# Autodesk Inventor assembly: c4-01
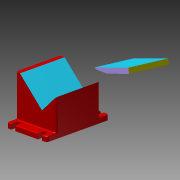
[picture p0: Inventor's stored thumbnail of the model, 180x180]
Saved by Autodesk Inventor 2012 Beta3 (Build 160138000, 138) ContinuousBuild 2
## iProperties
Created: 2010-11
Part Number: c4-01
Document SubType Name: Assembly
Designer: Beta-8540w
Author: Beta-8540w
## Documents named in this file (3)
- C:\Inventor 2012 Essentials\Assemblies\Chapter 4\c4-01.iam
- C:\Inventor 2012 Essentials\Parts\Chapter 4\c4-01.ipt
- C:\Inventor 2012 Essentials\Parts\Chapter 4\c4-02.ipt
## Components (2 placed, 2 different names)
1. c4-01:1
2. c4-02:1
